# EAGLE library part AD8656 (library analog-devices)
Low Noise, Precision CMOS Amplifier Source: http://www.analog.com/static/imported-files/data_sheets/AD8655_8656.pdf
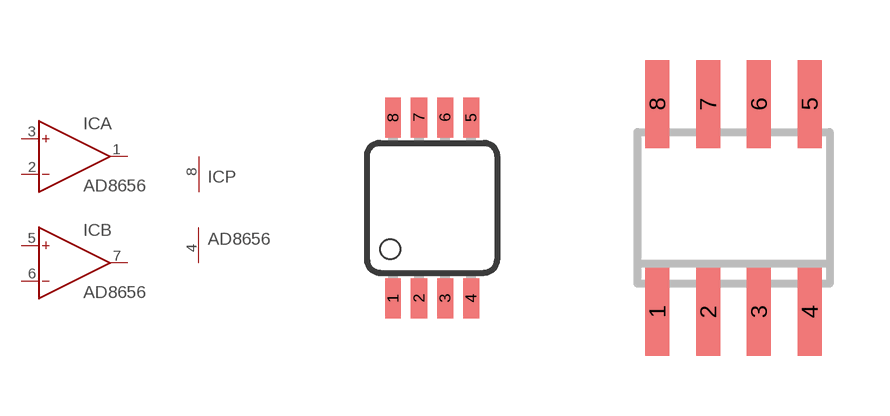
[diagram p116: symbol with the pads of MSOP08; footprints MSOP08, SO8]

Designator prefix IC; gates A=OP B=OP P=PWR+-

## AD8656RM (MPN: AD8656ARMZ; OC_FARNELL: 1117887; OC_NEWARK: 34P3252)  [MSOP08]
1  A:OUT  out
2  A:IN-  in
3  A:IN+  in
4  P:V-  pwr
5  B:IN+  in
6  B:IN-  in
7  B:OUT  out
8  P:V+  pwr

## AD8656R (MPN: AD8656ARZ; OC_FARNELL: 1117887; OC_NEWARK: 19M0993)  [SO8]
Pads as for MSOP08

## Footprint MSOP08 (pad centres in mm)
8-Lead micro SO (RM-8) Source: http://www.analog.com/UploadedFiles/Data_Sheets/703465986AD8611_2_0.pdf
smd 0.4 x 1: 1 -0.976,-2.263; 2 -0.326,-2.263; 3 0.324,-2.263; 4 0.974,-2.263; 5 0.974,2.262; 6 0.324,2.262; 7 -0.326,2.262; 8 -0.976,2.262

## Footprint SO8 (pad centres in mm)
8-Lead Small Outline IC (SO-8) Source: http://www.analog.com/UploadedFiles/Data_Sheets/703465986AD8611_2_0.pdf
smd 0.6 x 2.2: 1 -1.905,-2.6; 2 -0.635,-2.6; 3 0.635,-2.6; 4 1.905,-2.6; 5 1.905,2.6; 6 0.635,2.6; 7 -0.635,2.6; 8 -1.905,2.6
